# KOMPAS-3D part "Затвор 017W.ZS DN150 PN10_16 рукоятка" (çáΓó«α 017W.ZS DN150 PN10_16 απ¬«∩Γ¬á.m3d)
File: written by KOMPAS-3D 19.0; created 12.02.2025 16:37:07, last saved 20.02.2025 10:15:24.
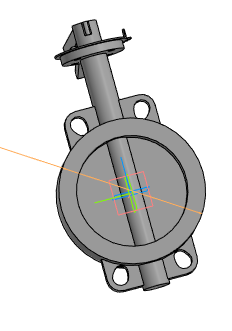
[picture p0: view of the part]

Document properties: Автор: Евгений; Полное имя файла: Затвор 017W.ZS DN150 PN10_16 рукоятка.a3d

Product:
- Part/product: Затвор 017W.ZS DN150 PN10_16 рукоятка
    Масса: 19.4807
  - Body: Тело 1
      Масса: 12.7995

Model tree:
1. Операция без истории:1
2. Диаметральный размер:1  (with: Операция без истории:1)
     Значение = 205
